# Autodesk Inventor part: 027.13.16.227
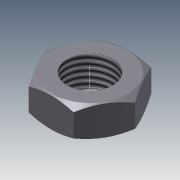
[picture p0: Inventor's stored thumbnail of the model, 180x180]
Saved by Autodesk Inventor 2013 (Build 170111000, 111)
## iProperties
Shininess: 64.0
Length Units: 11269
Angle Units: 11279
Time Units: 11290
Mass Units: 11283
Length Display Precision: 3
Angle Display Precision: 2
Created: 2002-02
Part Number: 027.13.16.227
Material: Steel, Mild
Document SubType Name: Modeling
Designer: SOleg
Density: 7.86 g/cm^3
Density: 0.0
Volumn: 0.0
Area: 0.0
PropertySet Name: Model Information
Control State: 0
Master: False
Checked Out: True
Author: SOleg
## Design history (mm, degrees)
sketch "Sketch1"
  geometry: L1 (9.815, 17)-(19.63, 0); L2 (19.63, 0)-(9.815, -17); L3 (9.815, -17)-(-9.815, -17); L4 (-9.815, -17)-(-19.63, 0); L5 (-19.63, 0)-(-9.815, 17); L6 (-9.815, 17)-(9.815, 17); C1 r 10 at (0, 0); 3 further points
  constraints: 12 end point, 2 coincident, 1 centre point, 1 midpoint, 1 vertical alignment, 13 other
  dimensions: "d1" = 20 diameter of C1
extrude "Extrusion1" new body sketch "Sketch1" distance "d2" = 13.5; taper "d3" = 0 deg
node "РабОсь1"
sketch "Sketch2"
  geometry: L1 (-16.5, 13.5)-(-19.942, 13.5); L2 (0, 45)-(0, -1.383); L3 (-16.5, 13.5)-(-19.942, 11.513); L4 (-19.942, 11.513)-(-19.942, 13.5); L5 (17, 0)-(17, 13.5) reference; L6 (17, 6.75)-(-24.004, 6.75); L7 (-16.5, 0)-(-19.942, 0); L8 (-16.5, 0)-(-19.942, 1.987); L9 (-19.942, 1.987)-(-19.942, 0); L10 (0, -10.66)-(0, 54.277) reference; L11 (10, 0)-(-10, 0) reference; L12 (17, 0)-(0, 0) reference; L13 (0, 0)-(-17, 0) reference; L14 (-17, 0)-(0, 0) reference; L15 (0, 0)-(17, 0) reference; L16 (-10, 13.5)-(10, 13.5) reference; L17 (17, 13.5)-(0, 13.5) reference; L18 (0, 13.5)-(17, 13.5) reference; L19 (-17, 13.5)-(0, 13.5) reference; L20 (0, 13.5)-(-17, 13.5) reference
  constraints: 16 end point, 3 collinear, 3 symmetric about line, 2 perpendicular, 1 midpoint, 3 other
  dimensions: "d5" = 30 deg angle of L1 L3; "d9" = 33 diameter of L7.start L2
revolve "Revolution1" sketch "Sketch2" stored, may be unused: angle "d6" = 90 deg
thread "Thread1" dims "d7" = 10, "d8" = 0
body "Solid1"
node "Спроецированная петля1"
node "Спроецированная петля2"
other parameters: "d0" = 34
